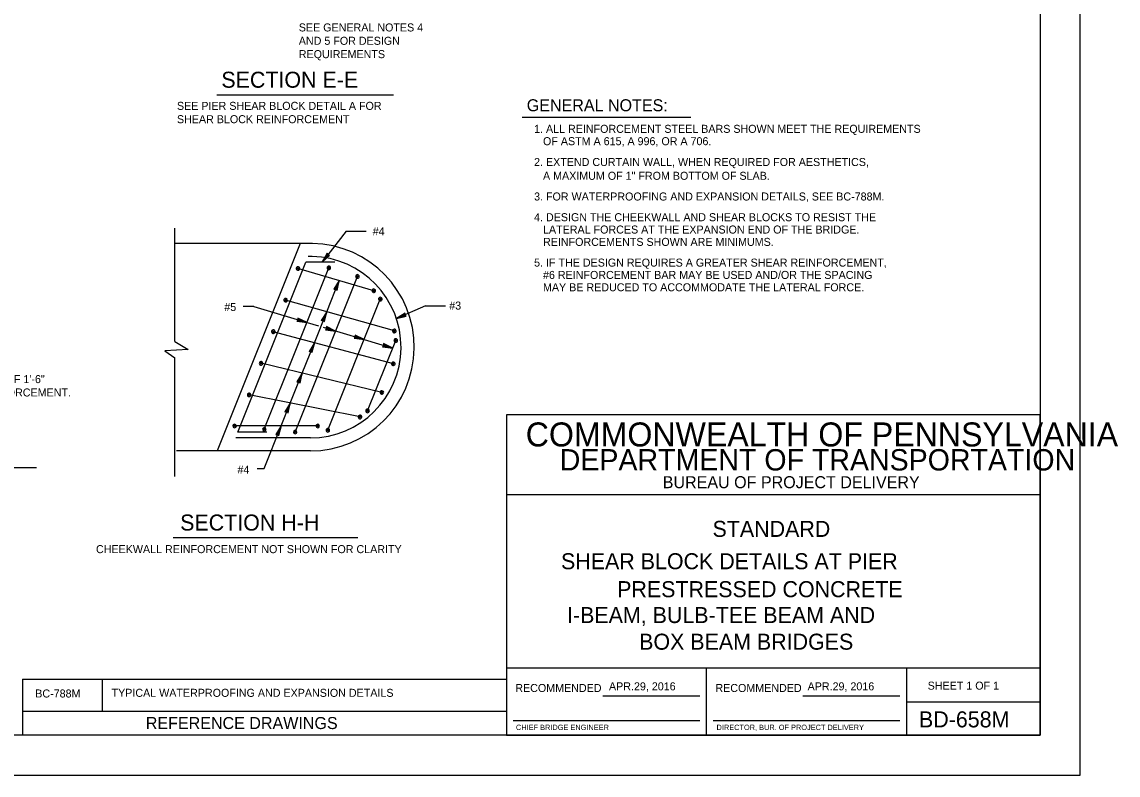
# Model space of a CAD drawing. Extents: x 638091 to 638946, y 298288 to 298882.
# Drawn here: x 638535 to 638945.8, y 298287.5 to 298569.7 of the extents above; entities that cross this region are included whole.
import ezdxf

# ---------------------------------------------------------------- set-up
doc = ezdxf.new("R2010")
doc.units = 0
for name, color, linetype in [('1', 7, 'Continuous'), ('2', 7, 'Continuous'), ('40', 7, 'Continuous'), ('PLT-BNDY', 7, 'Continuous')]:
    doc.layers.add(name, color=color, linetype=linetype)

msp = doc.modelspace()

# ---------------------------------------------------------------- linework, layer by layer
at = {"layer": '1'}
for p, q in [((638791.58, 298302.5), (638791.58, 298327.5)), ((638752.67, 298317.22), (638789.08, 298317.22)), ((638827.67, 298317.22), (638864.08, 298317.22)), ((638719.08, 298308), (638789.08, 298308)), ((638794.08, 298308), (638864.08, 298308))]:
    msp.add_line(p, q, dxfattribs=at)
at = {"layer": '2'}
for p, q in [((638916.58, 298866.5), (638916.58, 298302.5)), ((638608.01, 298542.41), (638674.26, 298542.41)), ((638722.5, 298534.05), (638785.68, 298534.05)), ((638656.58, 298491.25), (638664.08, 298491.25)), ((638638.28, 298476.65), (638638.38, 298476.99)), ((638649.8, 298476.91), (638649.94, 298477.24)), ((638649.26, 298461.09), (638653.93, 298472.77)), ((638660.5, 298473.7), (638660.63, 298474.03)), ((638666.72, 298468.33), (638666.82, 298468.67)), ((638621.99, 298463.03), (638617.9, 298463.03)), ((638621.99, 298463.03), (638641.87, 298457.08)), ((638633.66, 298464.81), (638633.76, 298465.16)), ((638669.09, 298465.23), (638669.23, 298465.56)), ((638686.28, 298463.3), (638693.78, 298463.3)), ((638644.63, 298449.52), (638649.26, 298461.09)), ((638641.87, 298457.08), (638646.21, 298455.79)), ((638647.9, 298455.28), (638654.17, 298453.41)), ((638629.05, 298452.98), (638629.14, 298453.32)), ((638654.17, 298453.41), (638663.27, 298450.68)), ((638663.27, 298450.68), (638673.97, 298447.48)), ((638674.43, 298453.27), (638674.53, 298453.61)), ((638637.95, 298447.3), (638637.95, 298447.3)), ((638640.05, 298438.08), (638644.63, 298449.52)), ((638674.86, 298449.7), (638674.99, 298450.03)), ((638624.81, 298442.44), (638624.73, 298442.1)), ((638635.58, 298426.9), (638640.05, 298438.08)), ((638659.21, 298440.53), (638659.21, 298440.53)), ((638674.06, 298440.96), (638674.15, 298441.31)), ((638669.83, 298437.14), (638669.83, 298437.14)), ((638620.3, 298430.62), (638620.23, 298430.27)), ((638670.09, 298431.52), (638670.01, 298431.18)), ((638632.14, 298418.3), (638635.58, 298426.9)), ((638661.86, 298422.36), (638661.79, 298422.01)), ((638664.81, 298424.58), (638664.68, 298424.25)), ((638916.58, 298422.5), (638716.58, 298422.5)), ((638716.58, 298422.5), (638716.58, 298302.5)), ((638916.58, 298302.5), (638916.58, 298422.5)), ((638614.72, 298418.97), (638614.72, 298418.61)), ((638625.75, 298402.33), (638632.14, 298418.3)), ((638625.87, 298417.72), (638625.87, 298417.37)), ((638645.88, 298418.97), (638645.88, 298418.61)), ((638637.44, 298416.72), (638637.44, 298416.36)), ((638649.92, 298417.31), (638649.79, 298416.97)), ((638470.63, 298402.78), (638540.43, 298402.78)), ((638623.23, 298402.33), (638625.75, 298402.33)), ((638916.58, 298392.5), (638716.58, 298392.5)), ((638591.75, 298376.5), (638660.96, 298376.5)), ((638916.58, 298327.5), (638716.58, 298327.5)), ((638866.58, 298327.5), (638866.58, 298302.5)), ((638535.3, 298323.5), (638716.58, 298323.5)), ((638535.3, 298323.5), (638535.3, 298302.5)), ((638565.18, 298311.5), (638565.18, 298323.5)), ((638866.58, 298315), (638916.58, 298315)), ((638535.3, 298311.5), (638716.58, 298311.5)), ((638916.58, 298302.5), (638130.58, 298302.5)), ((638716.58, 298302.5), (638916.58, 298302.5))]:
    msp.add_line(p, q, dxfattribs=at)
for points in [[(638649.49, 298482.75), (638649.51, 298482.57), (638647.56, 298479.66), (638649.49, 298482.75), (638649.37, 298483), (638647.56, 298479.66), (638649.81, 298482.34), (638650.08, 298482.29), (638647.56, 298479.66), (638650.35, 298482.23), (638650.08, 298482.29)], [(638652.93, 298469.26), (638652.86, 298469.43), (638653.93, 298472.77), (638652.93, 298469.26), (638653.11, 298469.06), (638653.93, 298472.77), (638652.51, 298469.57), (638652.23, 298469.54), (638653.93, 298472.77), (638651.95, 298469.52), (638652.23, 298469.54)], [(638638.29, 298457.76), (638638.44, 298457.85), (638641.87, 298457.08), (638638.29, 298457.76), (638638.1, 298457.56), (638641.87, 298457.08), (638638.55, 298458.21), (638638.5, 298458.48), (638641.87, 298457.08), (638638.45, 298458.76), (638638.5, 298458.48)], [(638648.2, 298457.61), (638648.13, 298457.77), (638649.26, 298461.09), (638648.2, 298457.61), (638648.38, 298457.39), (638649.26, 298461.09), (638647.79, 298457.91), (638647.51, 298457.9), (638649.26, 298461.09), (638647.23, 298457.88), (638647.51, 298457.9)], [(638678.58, 298460.3), (638678.51, 298460.14), (638675.34, 298458.63), (638678.58, 298460.3), (638678.61, 298460.58), (638675.34, 298458.63), (638678.65, 298459.79), (638678.86, 298459.6), (638675.34, 298458.63), (638679.06, 298459.41), (638678.86, 298459.6)], [(638648.99, 298454.56), (638649.14, 298454.65), (638652.57, 298453.88), (638648.99, 298454.56), (638648.8, 298454.36), (638652.57, 298453.88), (638649.25, 298455.01), (638649.2, 298455.28), (638652.57, 298453.88), (638649.15, 298455.56), (638649.2, 298455.28)], [(638659.69, 298451.36), (638659.84, 298451.45), (638663.27, 298450.68), (638659.69, 298451.36), (638659.5, 298451.16), (638663.27, 298450.68), (638659.95, 298451.8), (638659.9, 298452.08), (638663.27, 298450.68), (638659.85, 298452.36), (638659.9, 298452.08)], [(638592.29, 298449.96), (638597.35, 298446.96), (638588.54, 298446.4), (638592.29, 298443.78)], [(638643.63, 298446.01), (638643.56, 298446.17), (638644.63, 298449.52), (638643.63, 298446.01), (638643.82, 298445.8), (638644.63, 298449.52), (638643.21, 298446.31), (638642.93, 298446.29), (638644.63, 298449.52), (638642.66, 298446.26), (638642.93, 298446.29)], [(638670.39, 298448.16), (638670.54, 298448.24), (638673.97, 298447.48), (638670.39, 298448.16), (638670.2, 298447.96), (638673.97, 298447.48), (638670.65, 298448.6), (638670.6, 298448.88), (638673.97, 298447.48), (638670.55, 298449.15), (638670.6, 298448.88)], [(638639.06, 298434.57), (638638.99, 298434.74), (638640.05, 298438.08), (638639.06, 298434.57), (638639.24, 298434.36), (638640.05, 298438.08), (638638.64, 298434.87), (638638.36, 298434.85), (638640.05, 298438.08), (638638.08, 298434.83), (638638.36, 298434.85)], [(638634.58, 298423.39), (638634.51, 298423.55), (638635.58, 298426.9), (638634.58, 298423.39), (638634.77, 298423.18), (638635.58, 298426.9), (638634.16, 298423.69), (638633.88, 298423.67), (638635.58, 298426.9), (638633.6, 298423.65), (638633.88, 298423.67)], [(638631.14, 298414.79), (638631.07, 298414.96), (638632.14, 298418.3), (638631.14, 298414.79), (638631.33, 298414.59), (638632.14, 298418.3), (638630.72, 298415.1), (638630.44, 298415.07), (638632.14, 298418.3), (638630.17, 298415.05), (638630.44, 298415.07)]]:
    msp.add_lwpolyline(points, dxfattribs=at)
for centre in [(638638.47, 298477.29), (638650.05, 298477.53), (638660.75, 298474.33), (638666.9, 298468.97), (638633.84, 298465.46), (638669.34, 298465.86), (638629.22, 298453.63), (638674.61, 298453.91), (638675.11, 298450.33), (638624.65, 298441.79), (638674.22, 298441.61), (638620.16, 298429.96), (638669.93, 298430.87), (638661.73, 298421.7), (638664.56, 298423.96), (638614.72, 298418.3), (638645.87, 298418.3), (638625.87, 298417.05), (638637.43, 298416.04), (638649.67, 298416.68)]:
    msp.add_circle(centre, 0.314, dxfattribs=at)
for centre, start, end in [((638638.47, 298477.29), 255.0814, 254.0748), ((638650.05, 298477.53), 249.592, 248.5854), ((638660.75, 298474.33), 249.592, 248.5854), ((638666.9, 298468.97), 255.0814, 254.0748), ((638633.84, 298465.46), 255.5784, 254.5719), ((638669.34, 298465.86), 249.592, 248.5854), ((638674.61, 298453.91), 255.5784, 254.5719), ((638629.22, 298453.63), 256.4441, 255.4376), ((638675.11, 298450.33), 249.592, 248.5854), ((638624.65, 298441.79), 76.0543, 75.0478), ((638674.22, 298441.61), 256.4441, 255.4376), ((638620.16, 298429.96), 78.3742, 77.3677), ((638669.93, 298430.87), 76.0543, 75.0478), ((638661.73, 298421.7), 78.3742, 77.3677), ((638664.56, 298423.96), 67.8112, 66.8046), ((638614.72, 298418.3), 89.6129, 88.6064), ((638625.87, 298417.05), 89.6129, 88.6064), ((638645.87, 298418.3), 89.6129, 88.6064), ((638637.43, 298416.04), 89.6129, 88.6064), ((638649.67, 298416.68), 67.8112, 66.8046)]:
    msp.add_arc(centre, 0.671, start, end, dxfattribs=at)
at = {"layer": '40'}
for p, q in [((638592.29, 298449.96), (638592.29, 298492.43)), ((638656.58, 298491.25), (638647.56, 298479.66)), ((638643.9, 298486.68), (638592.29, 298486.68)), ((638639.34, 298486.68), (638608.25, 298408.97)), ((638616, 298416), (638641.46, 298479.66)), ((638652.31, 298479.66), (638641.46, 298479.66)), ((638643.81, 298481.83), (638642.33, 298481.83)), ((638625.86, 298417.06), (638650.05, 298477.53)), ((638666.9, 298468.97), (638638.47, 298477.29)), ((638638.47, 298477.29), (638638.47, 298477.29)), ((638638.47, 298477.29), (638638.47, 298477.29)), ((638637.43, 298416.04), (638660.75, 298474.33)), ((638633.72, 298465.49), (638633.72, 298465.49)), ((638633.84, 298465.46), (638633.84, 298465.46)), ((638674.61, 298453.91), (638633.84, 298465.46)), ((638649.67, 298416.68), (638669.34, 298465.86)), ((638686.28, 298463.3), (638675.34, 298458.63)), ((638628.97, 298453.7), (638628.97, 298453.7)), ((638629.22, 298453.63), (638629.22, 298453.63)), ((638674.22, 298441.61), (638629.22, 298453.63)), ((638629.22, 298453.63), (638629.22, 298453.63)), ((638664.56, 298423.96), (638675.11, 298450.33)), ((638592.29, 298399.33), (638592.29, 298443.78)), ((638624.22, 298441.9), (638624.22, 298441.9)), ((638624.64, 298441.8), (638624.64, 298441.8)), ((638624.64, 298441.8), (638624.64, 298441.8)), ((638669.93, 298430.87), (638624.65, 298441.79)), ((638624.65, 298441.79), (638624.65, 298441.79)), ((638619.47, 298430.1), (638619.47, 298430.1)), ((638661.73, 298421.7), (638620.16, 298429.96)), ((638620.17, 298429.96), (638620.17, 298429.96)), ((638620.17, 298429.96), (638620.17, 298429.96)), ((638614.72, 298418.3), (638614.72, 298418.3)), ((638645.87, 298418.3), (638614.72, 298418.3)), ((638614.72, 298418.3), (638614.72, 298418.3)), ((638614.72, 298418.3), (638614.72, 298418.3)), ((638643.12, 298413.83), (638615.13, 298413.83)), ((638626.85, 298416), (638616, 298416)), ((638643.11, 298408.97), (638593.01, 298408.97))]:
    msp.add_line(p, q, dxfattribs=at)
for centre, radius, start, end in [((638643.2, 298447.83), 38.85, 269.8619, 88.9735), ((638643.1, 298447.83), 34, 270.0241, 88.8113)]:
    msp.add_arc(centre, radius, start, end, dxfattribs=at)
at = {"layer": 'PLT-BNDY'}
msp.add_lwpolyline([(638090.58, 298287.5), (638931.58, 298287.5), (638931.58, 298881.5), (638090.58, 298881.5)], close=True, dxfattribs=at)

# ---------------------------------------------------------------- texts
at = {"layer": '1'}
for s, height, p in [('RECOMMENDED', 3, (638719.92, 298318.63)), ('APR.29, 2016', 3, (638755.03, 298319.25)), ('RECOMMENDED', 3, (638794.92, 298318.63)), ('APR.29, 2016', 3, (638829.46, 298319.25)), ('CHIEF BRIDGE ENGINEER', 2.0002, (638720.17, 298304.38)), ('DIRECTOR, BUR. OF PROJECT DELIVERY', 2.0002, (638795.34, 298304.38))]:
    msp.add_text(s, height=height, dxfattribs=at).set_placement(p)
at = {"layer": '2'}
for s, height, p in [('SEE GENERAL NOTES 4', 3, (638638.79, 298566.13)), ('AND 5 FOR DESIGN', 3, (638638.79, 298561.13)), ('REQUIREMENTS', 3, (638638.79, 298556.13)), ('SECTION E-E', 6.0003, (638609.76, 298545.04)), ('GENERAL NOTES:', 4.5, (638724.22, 298536.22)), ('SEE PIER SHEAR BLOCK DETAIL A FOR', 3, (638593.12, 298536.75)), ('SHEAR BLOCK REINFORCEMENT', 3, (638593.12, 298531.75)), ('2. EXTEND CURTAIN WALL, WHEN REQUIRED FOR AESTHETICS,', 3, (638726.96, 298515.71)), ('   A MAXIMUM OF 1" FROM BOTTOM OF SLAB.', 3, (638726.96, 298510.55)), ('3. FOR WATERPROOFING AND EXPANSION DETAILS, SEE BC-788M.', 3, (638726.96, 298502.79)), ('4. DESIGN THE CHEEKWALL AND SHEAR BLOCKS TO RESIST THE', 3, (638726.96, 298495.03)), ('#4', 3, (638666.48, 298489.72)), ('   LATERAL FORCES AT THE EXPANSION END OF THE BRIDGE.', 3, (638726.96, 298490.41)), ('   REINFORCEMENTS SHOWN ARE MINIMUMS.', 3, (638726.96, 298485.78)), ('5. IF THE DESIGN REQUIRES A GREATER SHEAR REINFORCEMENT,', 3, (638726.96, 298478.02)), ('   #6 REINFORCEMENT BAR MAY BE USED AND/OR THE SPACING', 3, (638726.96, 298473.4)), ('   MAY BE REDUCED TO ACCOMMODATE THE LATERAL FORCE.', 3, (638726.96, 298468.77)), ('#5', 3, (638610.86, 298461.38)), ('#3', 3, (638695.16, 298461.92)), ('USE EMBEDMENT OF 1\'-6"', 3, (638492.78, 298434.36)), ('FOR EPOXY REINFORCEMENT.', 3, (638492.78, 298429.36)), ('COMMONWEALTH OF PENNSYLVANIA', 9, (638723.83, 298410.63)), ('DEPARTMENT OF TRANSPORTATION', 8.0002, (638736.58, 298401.63)), ('#4', 3, (638615.81, 298400.45)), ('BUREAU OF PROJECT DELIVERY', 4.5, (638775.18, 298395)), ('SECTION H-H', 6.0002, (638594.32, 298379.13)), ('STANDARD', 6, (638793.83, 298376.75)), ('CHEEKWALL REINFORCEMENT NOT SHOWN FOR CLARITY', 2.9999, (638562.78, 298370.66)), ('SHEAR BLOCK DETAILS AT PIER', 6, (638737.06, 298364.63)), ('PRESTRESSED CONCRETE', 6, (638758.08, 298354.16)), ('I-BEAM, BULB-TEE BEAM AND', 6, (638739.31, 298344.47)), ('BOX BEAM BRIDGES ', 6, (638766.33, 298334.48)), ('BC-788M', 3, (638540.02, 298316.57)), ('TYPICAL WATERPROOFING AND EXPANSION DETAILS', 3, (638568.62, 298316.82)), ('SHEET 1 OF 1', 3, (638874.46, 298319.51)), ('BD-658M', 6, (638871.21, 298305.38)), ('REFERENCE DRAWINGS', 4.5, (638581.46, 298304.75))]:
    msp.add_text(s, height=height, dxfattribs=at).set_placement(p)
at = {"layer": '40'}
for s, p in [('1. ALL REINFORCEMENT STEEL BARS SHOWN MEET THE REQUIREMENTS', (638726.96, 298528.14)), ('   OF ASTM A 615, A 996, OR A 706.', (638726.96, 298523.51))]:
    msp.add_text(s, height=3, dxfattribs=at).set_placement(p)

doc.saveas('drawing.dxf')
